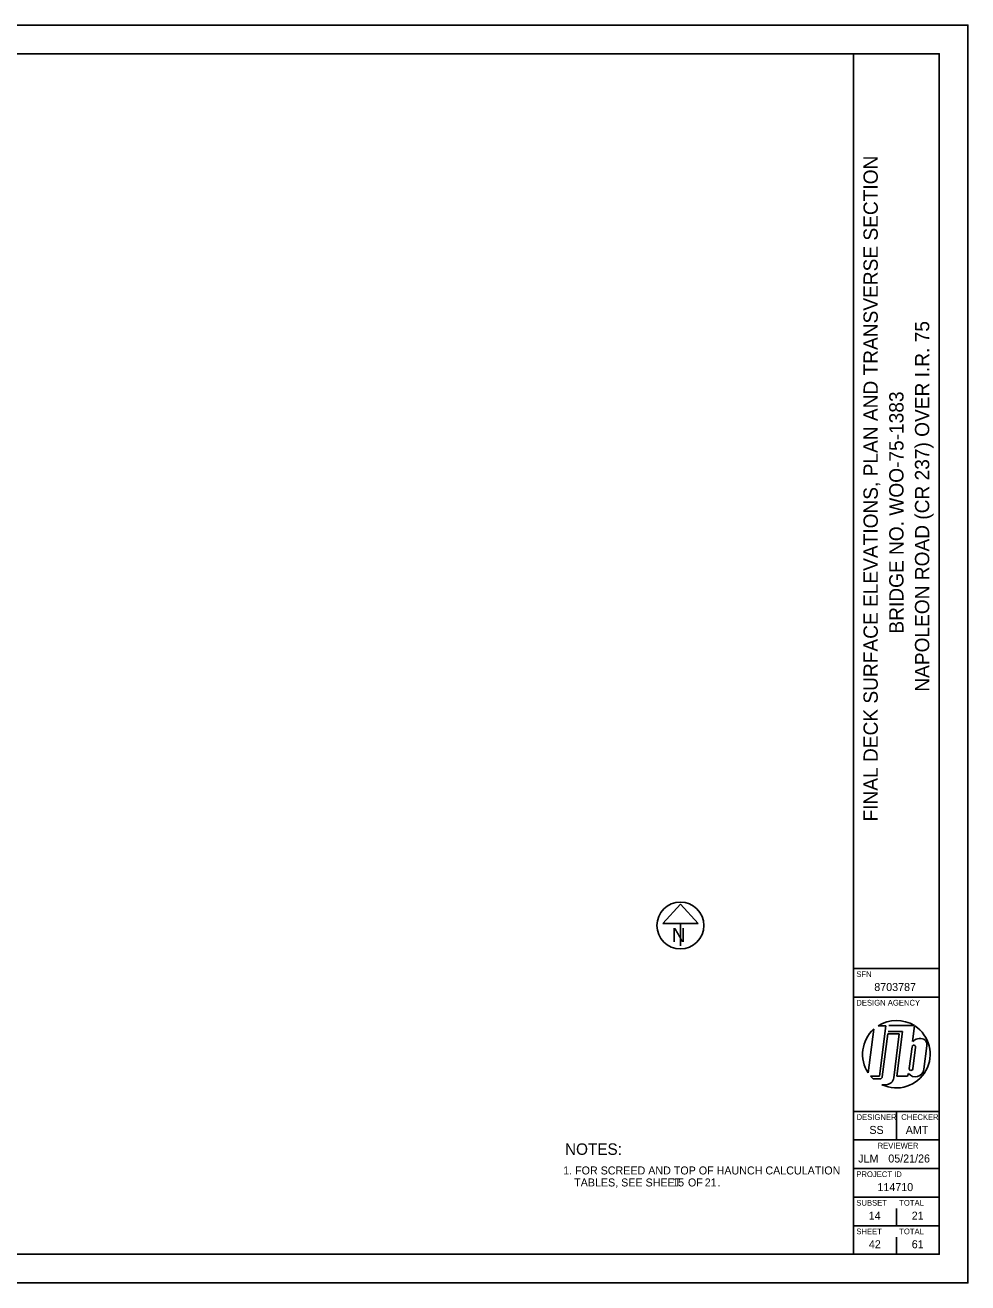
# Model space of a CAD drawing. Extents: x 0 to 114, y 0 to 22.
# Drawn here: x 17.51 to 34, y 0 to 22 of the extents above; entities that cross this region are included whole.
import ezdxf

# ---------------------------------------------------------------- set-up
doc = ezdxf.new("R2010")
doc.units = 0
for name, color, linetype in [('BR_P_Beam_Const_Joint', 7, 'Continuous'), ('BR_X_Beam_Object', 7, 'Continuous'), ('BR_X_Det_Centerline', 7, 'Continuous'), ('BR_X_Gen_Porous_Backfill', 7, 'Continuous'), ('BR_X_Sub_Deep_Centerline', 7, 'Continuous'), ('Default', 7, 'Continuous')]:
    doc.layers.add(name, color=color, linetype=linetype)

msp = doc.modelspace()

# ---------------------------------------------------------------- linework, layer by layer
at = {"layer": 'BR_P_Beam_Const_Joint'}
for p, q in [((32.356, 4.44), (32.259, 3.671)), ((32.432, 4.498), (32.567, 4.498)), ((32.567, 4.498), (32.456, 3.618)), ((32.617, 4.5), (33.065, 4.5)), ((33.07, 4.496), (33.035, 4.22)), ((32.504, 3.604), (32.599, 4.355)), ((32.599, 4.355), (32.801, 4.355)), ((32.856, 4.396), (32.604, 4.396)), ((32.801, 4.355), (32.704, 3.589)), ((32.758, 3.618), (32.856, 4.396)), ((32.75, 4), (32.75, 4)), ((33.024, 4.131), (32.976, 3.75)), ((33.036, 3.743), (33.084, 4.124)), ((33.283, 4.148), (33.231, 3.737)), ((32.456, 3.618), (32.299, 3.618)), ((32.347, 3.568), (32.462, 3.568)), ((32.947, 3.618), (32.758, 3.618)), ((32.964, 3.661), (32.947, 3.618)), ((32.564, 3.466), (32.498, 3.466)), ((32.75, 1), (32.75, 1.3)), ((32.375, 0.675), (32.375, 0.675)), ((32.75, 0.5), (32.75, 0.8))]:
    msp.add_line(p, q, dxfattribs=at)
for centre, radius, start, end in [((32.75, 4), 0.591, 131.8253, 213.7822), ((32.75, 4), 0.591, 57.726, 122.5688), ((32.75, 4), 0.591, 244.7646, 57.1575), ((33.17, 4.086), 0.19, 105.9444, 135.0487), ((33.164, 4.1), 0.175, 66.6782, 105.4185), ((33.177, 4.169), 0.108, 349.2072, 58.7163), ((33.054, 4.128), 0.0301, 352.3298, 173.2777), ((33.006, 3.746), 0.0301, 172.3335, 353.274), ((32.75, 4), 0.591, 220.2786, 227.0158), ((32.462, 3.609), 0.0417, 270, 352.8038), ((32.564, 3.606), 0.141, 270, 352.8038), ((33.081, 3.755), 0.151, 218.6264, 353.0883)]:
    msp.add_arc(centre, radius, start, end, dxfattribs=at)
at = {"layer": 'BR_X_Beam_Object'}
msp.add_lwpolyline([(0, 0), (34, 0), (34, 22), (0, 22)], close=True, dxfattribs=at)
at = {"layer": 'BR_X_Det_Centerline'}
for p, q in [((32, 0.5), (32, 21.5)), ((32, 5.5), (33.5, 5.5)), ((32, 5), (33.5, 5)), ((32, 3), (33.5, 3)), ((32.75, 3), (32.75, 2.5)), ((32, 2.5), (33.5, 2.5)), ((32, 2), (33.5, 2)), ((32, 1.5), (33.5, 1.5)), ((32, 1), (33.5, 1))]:
    msp.add_line(p, q, dxfattribs=at)
msp.add_lwpolyline([(1.5, 21.5), (33.5, 21.5), (33.5, 0.5), (1.5, 0.5)], close=True, dxfattribs=at)
at = {"layer": 'BR_X_Gen_Porous_Backfill'}
for p, q in [((28.973, 6.625), (28.666, 6.284)), ((29.281, 6.284), (28.973, 6.625)), ((28.666, 6.284), (29.281, 6.284)), ((28.973, 6.284), (28.973, 5.897))]:
    msp.add_line(p, q, dxfattribs=at)
msp.add_circle((28.973, 6.251), 0.41, dxfattribs=at)
at = {"layer": 'BR_X_Sub_Deep_Centerline'}
msp.add_circle((28.973, 6.251), 0.41, dxfattribs=at)

# ---------------------------------------------------------------- texts
at = {"layer": 'BR_P_Beam_Const_Joint'}
for s, p in [('FINAL DECK SURFACE ELEVATIONS, PLAN AND TRANSVERSE SECTION', (32.425, 8.07)), ('NAPOLEON ROAD (CR 237) OVER I.R. 75', (33.325, 10.34)), ('BRIDGE NO. WOO-75-1383', (32.875, 11.357))]:
    msp.add_text(s, height=0.25, rotation=90, dxfattribs=at).set_placement(p)
for s, height, p in [('SFN', 0.1, (32.05, 5.35)), ('8703787', 0.14, (32.364, 5.105)), ('DESIGN AGENCY', 0.1, (32.05, 4.85)), ('DESIGNER', 0.1, (32.054, 2.85)), ('CHECKER', 0.1, (32.835, 2.85)), ('SS', 0.14, (32.278, 2.605)), ('AMT', 0.14, (32.914, 2.605)), ('REVIEWER', 0.1, (32.422, 2.35)), ('JLM', 0.14, (32.083, 2.105)), ('05/21/26', 0.14, (32.609, 2.105)), ('PROJECT ID', 0.1, (32.05, 1.85)), ('114710', 0.14, (32.419, 1.605)), ('SUBSET', 0.1, (32.05, 1.35)), ('TOTAL', 0.1, (32.8, 1.35)), ('14', 0.14, (32.266, 1.105)), ('21', 0.14, (33.019, 1.105)), ('SHEET', 0.1, (32.05, 0.85)), ('TOTAL', 0.1, (32.8, 0.85)), ('42', 0.14, (32.269, 0.605)), ('61', 0.14, (33.019, 0.605))]:
    msp.add_text(s, height=height, dxfattribs=at).set_placement(p)
at = {"layer": 'BR_X_Gen_Porous_Backfill'}
msp.add_text('N', height=0.25, dxfattribs=at).set_placement((28.822, 5.96))
at = {"layer": 'Default'}
for s, height, p in [('NOTES:', 0.2, (26.955, 2.239)), ('1. FOR SCREED AND TOP OF HAUNCH CALCULATION ', 0.14, (26.923, 1.896)), (' TABLES, SEE SHEET ', 0.14, (27.063, 1.686)), ('15', 0.14, (28.829, 1.686)), (' OF ', 0.14, (29.053, 1.686)), ('21', 0.14, (29.398, 1.686)), ('.', 0.14, (29.622, 1.686))]:
    msp.add_text(s, height=height, dxfattribs=at).set_placement(p)

doc.saveas('drawing.dxf')
